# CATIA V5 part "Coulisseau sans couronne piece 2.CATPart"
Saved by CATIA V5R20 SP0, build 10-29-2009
Part number: coulisseau piece 2
Bounding box of the stored display mesh (mm): x -23.917 to 23.917, y 0 to 60, z -23.917 to 23.917
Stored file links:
  G:\Khaled_CFAO_2011\SIL\SIL_GR1\blaboucarri\Khaled\CAD_CATIA\Coulisseau sans couronne piece 2.CATPart
  C:\Users\Béatrice\Documents\IFMA\Cours\Semestre 3\CFAO\Think motion parapluie\Fina\Coulisseau et couronne.CATProduct
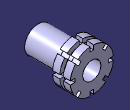
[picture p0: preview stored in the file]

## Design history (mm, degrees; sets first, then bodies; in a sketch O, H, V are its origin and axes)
Parameters
  `rayon de base` = 15 mm
  `Rayon max` = 24 mm
  `hauteur bas` = 40 mm
  `petite hauteur haut` = 8 mm
  `petite hauteur intermédiaire` = 4 mm
  `profondeur rainure couronne` = 5 mm
  `rayon intérieur` = 10 mm
Set1
  Sketch1, origin (0, -360.6617, 0), H (-0.0273, 0, 0.9996), V (0.9996, 0, 0.0273), geometry linked from another document
Body1 (main body)
  Sketch2 on xy-plane, origin (0, 0, 0), H (1, 0, 0), V (0, 1, 0)
    line L1 (0, 0) -> (-15, 0)
    line L2 (-15, 0) -> (-15, 40)
    line L3 (-15, 40) -> (-24, 40)
    line L4 (-24, 40) -> (-24, 48)
    line L5 (-24, 48) -> (-19, 48)
    line L6 (-19, 48) -> (-19, 52)
    line L7 (-19, 52) -> (-24, 52)
    point P7 (-24, 52)
    line L8 (-24, 52) -> (-24, 60)
    line L9 (-24, 60) -> (0, 60)
    point P9 (0, 60)
    line L10 (0, 60) -> (0, 0)
    length L9 = 24 {= `Rayon max`}
    length L8 = 8 {= `petite hauteur haut`}
    length L6 = 4 {= `petite hauteur intermédiaire`}
    length L4 = 8 {= `petite hauteur haut`}
    length L2 = 40 {= `hauteur bas`}
    length L1 = 15 {= `rayon de base`}
    length L7 = 5 {= `profondeur rainure couronne`}
    horizontal: L1 H, L3 H, L5 H, L7 H, L9 H
    vertical: L2 V, L4 V, L6 V, L8 V, L10 V
    coincidence: P7 L4, P9 V
  Shaft1: profile Sketch2, axis Sketch2.L10, angle 360
  Sketch3 on face of Shaft1 from Sketch2.L1, origin (0, 0, 0), H (1, 0, 0), V (0, 0, 1)
    point P1 (0, 0)
  Hole1: placed by Sketch3, at (0, 0, 0) direction (0, 1, 0), diameter 20 {= 2*`rayon intérieur`}, depth 80
  Plane1: type Offset, RefPlane face of Shaft1 from Sketch2.L5, Offset 2, reversed
  Sketch4 on face of Shaft1 from Sketch2.L9, origin (0, 60, 0), H (-1, 0, 0), V (0, 0, 1)
    line L1 (-2, 34) -> (2, 34)
    line L2 (2, 34) -> (2, 19)
    line L3 (2, 19) -> (-2, 19)
    line L4 (-2, 19) -> (-2, 34)
    axis line L5 (0, 0) -> (0, 39.1382)
    distance O L3 = 19
    length L2 = 15
    length L1 = 4
    horizontal: L1 H, L3 H
    vertical: L2 V, L4 V, L5 V
    symmetry: L2 L4 L5
  Pocket1: profile Sketch4, direction (0, -1, 0), up to face of Shaft1 from Sketch2.L3
  CircPattern1: of Pocket1, instances 8, angular step 45, axis from face of Shaft1 from Sketch2.L2
Body2
  Sketch5 on face of Shaft1 from Sketch2.L9, origin (0, 60, 0), H (-1, 0, 0), V (0, 0, 1)
  Pad1: profile Sketch5, direction (0, 1, 0), length 20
